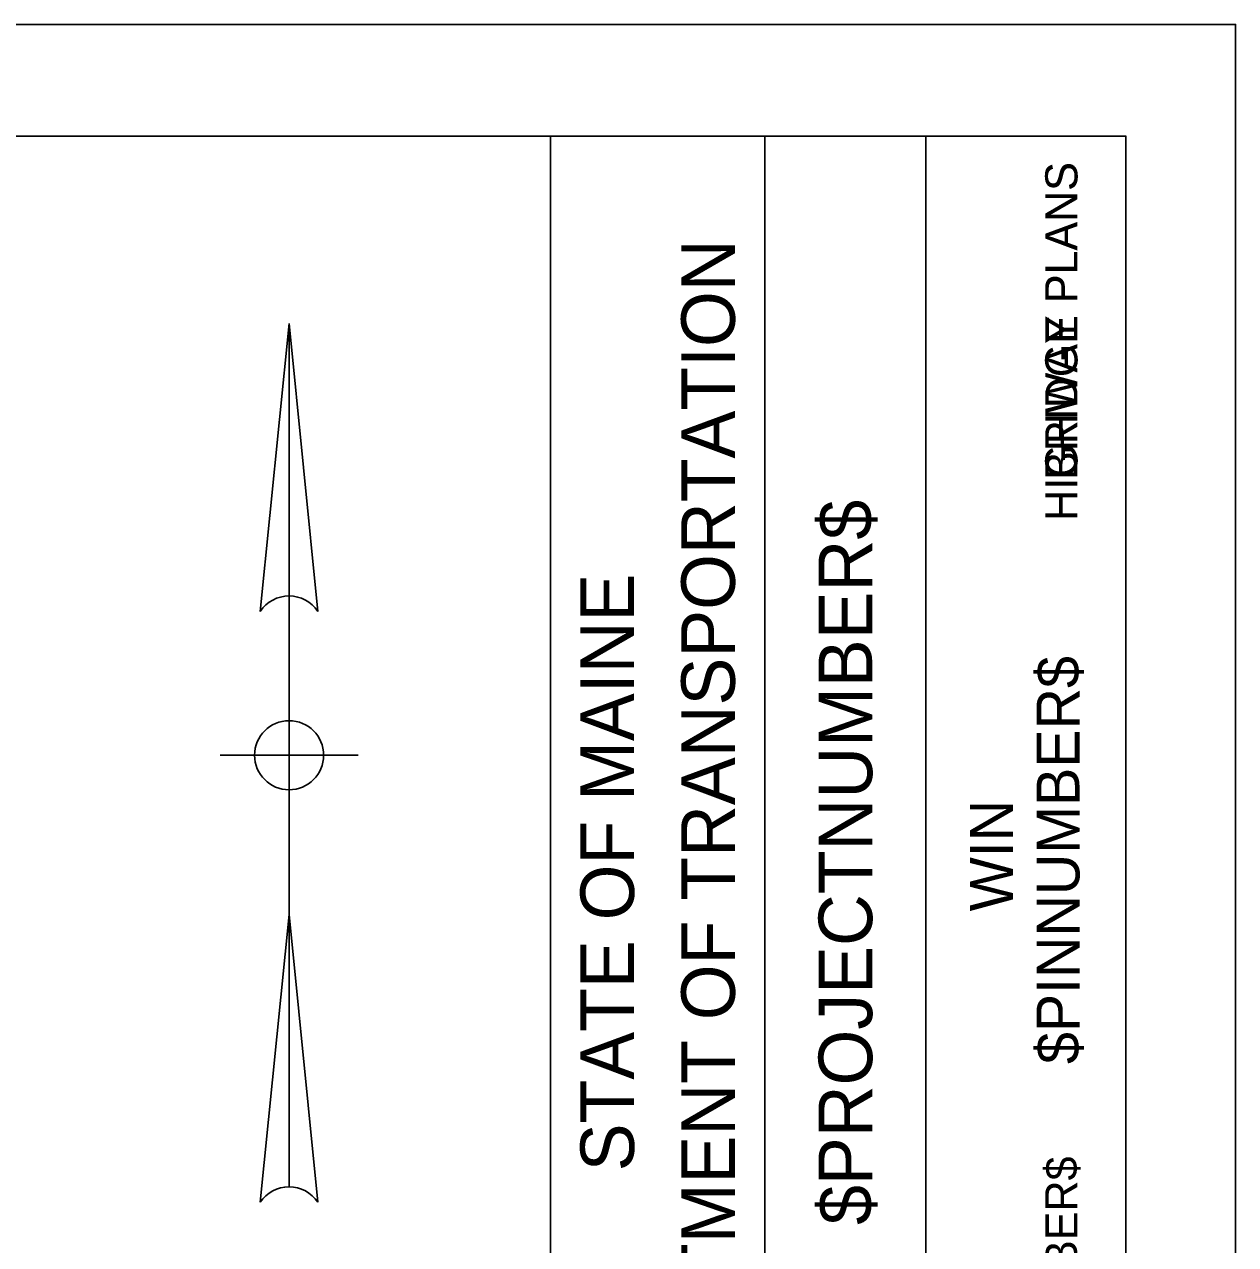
# Model space of a CAD drawing. Extents: x 9916 to 916479, y 6678 to 329942.
# Drawn here: x 916365.9 to 916471.2, y 329835.7 to 329941.7 of the extents above; entities that cross this region are included whole.
import ezdxf

# ---------------------------------------------------------------- set-up
doc = ezdxf.new("R2010")
doc.units = 0
for name, color, linetype in [('Border', 7, 'Continuous'), ('BRIDGE_TITLE', 7, 'Continuous'), ('H_V CONTROLS', 7, 'Continuous'), ('HIGHWAY_TITLE', 7, 'Continuous'), ('PLOT BOUNDARY', 7, 'Continuous')]:
    doc.layers.add(name, color=color, linetype=linetype)

msp = doc.modelspace()

# ---------------------------------------------------------------- linework, layer by layer
at = {"layer": 'Border'}
for p, q in [((916461.64, 329932), (915661.64, 329932)), ((916411.64, 329407.01), (916411.64, 329932.01)), ((916430.28, 329806.98), (916430.28, 329931.98)), ((916444.25, 329806.98), (916444.25, 329931.98)), ((916461.64, 329407.01), (916461.64, 329932.01))]:
    msp.add_line(p, q, dxfattribs=at)
at = {"layer": 'H_V CONTROLS'}
for p, q in [((916386.44, 329890.7), (916388.94, 329915.7)), ((916388.94, 329915.7), (916388.94, 329840.7)), ((916388.94, 329915.7), (916391.44, 329890.7)), ((916382.94, 329878.2), (916394.94, 329878.2)), ((916386.44, 329839.36), (916388.94, 329864.36)), ((916388.94, 329864.36), (916391.44, 329839.36))]:
    msp.add_line(p, q, dxfattribs=at)
msp.add_circle((916388.94, 329878.2), 3, dxfattribs=at)
for centre in [(916388.94, 329889.04), (916388.94, 329837.7)]:
    msp.add_arc(centre, 3, 33.5573, 146.4427, dxfattribs=at)
at = {"layer": 'PLOT BOUNDARY'}
msp.add_lwpolyline([(915621.17, 329391.7), (916471.17, 329391.7), (916471.17, 329941.7), (915621.17, 329941.7)], close=True, dxfattribs=at)

# ---------------------------------------------------------------- texts
at = {"layer": 'Border'}
for s, height, p in [('DEPARTMENT OF TRANSPORTATION', 4.6588, (916427.67, 329810.53)), ('$PROJECTNUMBER$', 4.6588, (916439.6, 329837.39)), ('STATE OF MAINE', 4.6588, (916418.91, 329842.05)), ('$PINNUMBER$', 3.7264, (916457.61, 329851.37)), ('WIN', 3.726, (916451.82, 329864.64))]:
    msp.add_text(s, height=height, rotation=90, dxfattribs=at).set_placement(p)
at = {"layer": 'BRIDGE_TITLE'}
for s, p in [('BRIDGE PLANS', (916457.43, 329902.12)), ('$BRIDGENUMBER$', (916457.43, 329808.65))]:
    msp.add_text(s, height=2.795, rotation=90, dxfattribs=at).set_placement(p)
at = {"layer": 'HIGHWAY_TITLE'}
msp.add_text('HIGHWAY PLANS', height=2.795, rotation=90, dxfattribs=at).set_placement((916457.43, 329898.57))

doc.saveas('drawing.dxf')
